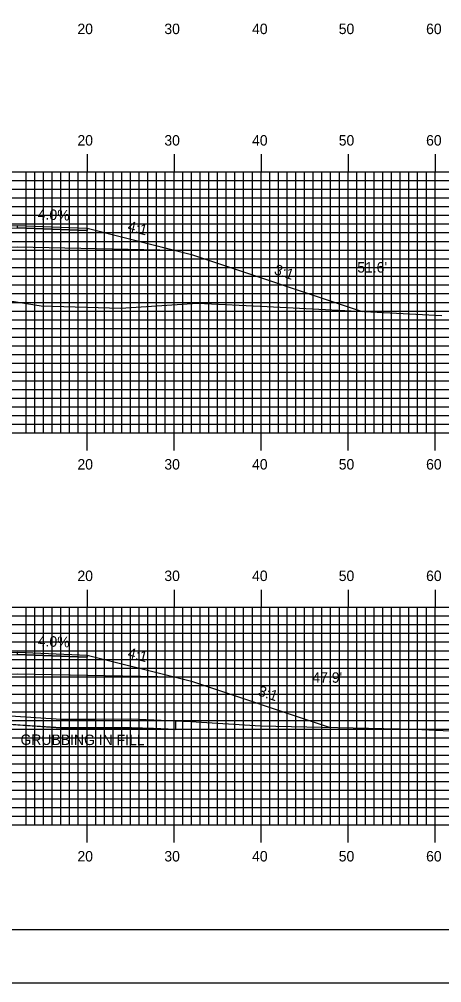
# Model space of a CAD drawing. Extents: x 1805471 to 1805814, y 442591 to 442811.
# Drawn here: x 1805648.9 to 1805697.5, y 442590.5 to 442701.2 of the extents above; entities that cross this region are included whole.
import ezdxf

# ---------------------------------------------------------------- set-up
doc = ezdxf.new("R2010")
doc.units = 0
for name, color, linetype in [('ANNOTATION', 7, 'Continuous'), ('BORDER', 7, 'Continuous'), ('D_Roadway_Centerline', 7, 'Continuous'), ('D_Roadway_Edge_Shoulder', 7, 'Continuous'), ('D_Roadway_SlopeLines', 7, 'Continuous'), ('D_Roadway_SubGrade', 7, 'Continuous'), ('D_Text_Standard', 7, 'Continuous'), ('GRUBBING IN FILL', 7, 'Continuous'), ('H_V ANNOTATION', 7, 'Continuous'), ('MAJOR', 7, 'Continuous'), ('MINOR', 7, 'Continuous'), ('PLOT BOUNDARY', 7, 'Continuous'), ('S_Roadway_Centerline', 7, 'Continuous')]:
    doc.layers.add(name, color=color, linetype=linetype)

msp = doc.modelspace()

# ---------------------------------------------------------------- linework, layer by layer
at = {"layer": 'BORDER'}
msp.add_lwpolyline([(1805487.11, 442596.67), (1805807.11, 442596.67), (1805807.11, 442806.67), (1805487.11, 442806.67)], close=True, dxfattribs=at)
at = {"layer": 'D_Roadway_Centerline'}
for points in [[(1805591.01, 442670.17), (1805604.71, 442673.6), (1805606.53, 442674.05), (1805616.71, 442676.6), (1805624.71, 442676.92), (1805636.71, 442677.21), (1805648.71, 442677.49), (1805656.71, 442677.17), (1805666.88, 442674.63), (1805668.71, 442674.17), (1805688.33, 442667.63)], [(1805599.16, 442623.21), (1805604.71, 442624.6), (1805606.53, 442625.05), (1805616.71, 442627.6), (1805624.71, 442627.92), (1805636.71, 442628.21), (1805648.71, 442628.49), (1805656.71, 442628.17), (1805666.88, 442625.63), (1805668.71, 442625.17), (1805684.65, 442619.86)]]:
    msp.add_lwpolyline(points, dxfattribs=at)
at = {"layer": 'D_Roadway_Edge_Shoulder'}
for points in [[(1805648.71, 442677.49), (1805656.71, 442677.17), (1805656.71, 442676.92), (1805648.71, 442677.24)], [(1805648.71, 442628.49), (1805656.71, 442628.17), (1805656.71, 442627.92), (1805648.71, 442628.24)]]:
    msp.add_lwpolyline(points, close=True, dxfattribs=at)
at = {"layer": 'D_Roadway_SlopeLines'}
for points in [[(1805656.71, 442677.17), (1805668.71, 442674.17), (1805688.33, 442667.63)], [(1805656.71, 442628.17), (1805668.71, 442625.17), (1805684.65, 442619.86)]]:
    msp.add_lwpolyline(points, dxfattribs=at)
at = {"layer": 'D_Roadway_SubGrade'}
for points in [[(1805624.71, 442674.42), (1805606.53, 442674.05), (1805616.71, 442676.6), (1805616.71, 442676.35), (1805624.71, 442676.67), (1805636.71, 442676.96), (1805648.71, 442677.24), (1805656.71, 442676.92), (1805656.71, 442677.17), (1805666.88, 442674.63), (1805648.71, 442674.99), (1805636.71, 442674.71)], [(1805624.71, 442625.42), (1805606.53, 442625.05), (1805616.71, 442627.6), (1805616.71, 442627.35), (1805624.71, 442627.67), (1805636.71, 442627.96), (1805648.71, 442628.24), (1805656.71, 442627.92), (1805656.71, 442628.17), (1805666.88, 442625.63), (1805648.71, 442625.99), (1805636.71, 442625.71)]]:
    msp.add_lwpolyline(points, close=True, dxfattribs=at)
at = {"layer": 'GRUBBING IN FILL'}
msp.add_line((1805666.88, 442620.62), (1805666.88, 442619.62), dxfattribs=at)
msp.add_line((1805666.88, 442620.62), (1805666.88, 442619.62), dxfattribs=at)
msp.add_lwpolyline([(1805606.53, 442621.76), (1805613.58, 442621.32), (1805617.1, 442621.11), (1805617.34, 442621.1), (1805617.7, 442621.08), (1805635.58, 442620.89), (1805644.34, 442620.45), (1805653.7, 442619.8), (1805661.81, 442619.83), (1805666.88, 442619.62)], dxfattribs=at)
msp.add_lwpolyline([(1805606.53, 442621.76), (1805613.58, 442621.32), (1805617.1, 442621.11), (1805617.34, 442621.1), (1805617.7, 442621.08), (1805635.58, 442620.89), (1805644.34, 442620.45), (1805653.7, 442619.8), (1805661.81, 442619.83), (1805666.88, 442619.62)], dxfattribs=at)
msp.add_lwpolyline([(1805636.71, 442621.83), (1805640.01, 442621.67), (1805644.4, 442621.44), (1805649.07, 442621.12), (1805653.73, 442620.8), (1805657.78, 442620.82), (1805661.83, 442620.83), (1805665.24, 442620.69), (1805666.88, 442620.62), (1805666.88, 442619.62), (1805664.35, 442619.73), (1805661.81, 442619.83), (1805657.76, 442619.82), (1805653.7, 442619.8), (1805649.02, 442620.12), (1805644.34, 442620.45), (1805639.96, 442620.67), (1805636.71, 442620.83)], close=True, dxfattribs=at)
msp.add_lwpolyline([(1805636.71, 442621.83), (1805640.01, 442621.67), (1805644.4, 442621.44), (1805649.07, 442621.12), (1805653.73, 442620.8), (1805657.78, 442620.82), (1805661.83, 442620.83), (1805665.24, 442620.69), (1805666.88, 442620.62), (1805666.88, 442619.62), (1805664.35, 442619.73), (1805661.81, 442619.83), (1805657.76, 442619.82), (1805653.7, 442619.8), (1805649.02, 442620.12), (1805644.34, 442620.45), (1805639.96, 442620.67), (1805636.71, 442620.83)], close=True, dxfattribs=at)
at = {"layer": 'MAJOR'}
for p, q in [((1805656.71, 442685.67), (1805656.71, 442683.67)), ((1805666.71, 442685.67), (1805666.71, 442683.67)), ((1805676.71, 442685.67), (1805676.71, 442683.67)), ((1805686.71, 442685.67), (1805686.71, 442683.67)), ((1805696.71, 442685.67), (1805696.71, 442683.67)), ((1805496.71, 442683.67), (1805776.71, 442683.67)), ((1805496.71, 442683.67), (1805776.71, 442683.67)), ((1805656.71, 442653.67), (1805656.71, 442683.67)), ((1805666.71, 442653.67), (1805666.71, 442683.67)), ((1805676.71, 442653.67), (1805676.71, 442683.67)), ((1805686.71, 442653.67), (1805686.71, 442683.67)), ((1805696.71, 442653.67), (1805696.71, 442683.67)), ((1805496.71, 442678.67), (1805776.71, 442678.67)), ((1805496.71, 442673.67), (1805776.71, 442673.67)), ((1805496.71, 442668.67), (1805776.71, 442668.67)), ((1805496.71, 442663.67), (1805776.71, 442663.67)), ((1805496.71, 442658.67), (1805776.71, 442658.67)), ((1805496.71, 442653.67), (1805776.71, 442653.67)), ((1805496.71, 442653.67), (1805776.71, 442653.67)), ((1805656.71, 442651.66), (1805656.71, 442653.67)), ((1805666.71, 442651.66), (1805666.71, 442653.67)), ((1805676.71, 442651.66), (1805676.71, 442653.67)), ((1805686.71, 442651.66), (1805686.71, 442653.67)), ((1805696.71, 442651.66), (1805696.71, 442653.67)), ((1805656.71, 442635.67), (1805656.71, 442633.67)), ((1805666.71, 442635.67), (1805666.71, 442633.67)), ((1805676.71, 442635.67), (1805676.71, 442633.67)), ((1805686.71, 442635.67), (1805686.71, 442633.67)), ((1805696.71, 442635.67), (1805696.71, 442633.67)), ((1805496.71, 442633.67), (1805776.71, 442633.67)), ((1805496.71, 442633.67), (1805776.71, 442633.67)), ((1805656.71, 442608.67), (1805656.71, 442633.67)), ((1805666.71, 442608.67), (1805666.71, 442633.67)), ((1805676.71, 442608.67), (1805676.71, 442633.67)), ((1805686.71, 442608.67), (1805686.71, 442633.67)), ((1805696.71, 442608.67), (1805696.71, 442633.67)), ((1805496.71, 442628.67), (1805776.71, 442628.67)), ((1805496.71, 442623.67), (1805776.71, 442623.67)), ((1805496.71, 442618.67), (1805776.71, 442618.67)), ((1805496.71, 442613.67), (1805776.71, 442613.67)), ((1805496.71, 442608.67), (1805776.71, 442608.67)), ((1805496.71, 442608.67), (1805776.71, 442608.67)), ((1805656.71, 442606.66), (1805656.71, 442608.67)), ((1805666.71, 442606.66), (1805666.71, 442608.67)), ((1805676.71, 442606.66), (1805676.71, 442608.67)), ((1805686.71, 442606.66), (1805686.71, 442608.67)), ((1805696.71, 442606.66), (1805696.71, 442608.67))]:
    msp.add_line(p, q, dxfattribs=at)
at = {"layer": 'MINOR'}
for p, q in [((1805649.71, 442653.67), (1805649.71, 442683.67)), ((1805650.71, 442653.67), (1805650.71, 442683.67)), ((1805651.71, 442653.67), (1805651.71, 442683.67)), ((1805652.71, 442653.67), (1805652.71, 442683.67)), ((1805653.71, 442653.67), (1805653.71, 442683.67)), ((1805654.71, 442653.67), (1805654.71, 442683.67)), ((1805655.71, 442653.67), (1805655.71, 442683.67)), ((1805657.71, 442653.67), (1805657.71, 442683.67)), ((1805658.71, 442653.67), (1805658.71, 442683.67)), ((1805659.71, 442653.67), (1805659.71, 442683.67)), ((1805660.71, 442653.67), (1805660.71, 442683.67)), ((1805661.71, 442653.67), (1805661.71, 442683.67)), ((1805662.71, 442653.67), (1805662.71, 442683.67)), ((1805663.71, 442653.67), (1805663.71, 442683.67)), ((1805664.71, 442653.67), (1805664.71, 442683.67)), ((1805665.71, 442653.67), (1805665.71, 442683.67)), ((1805667.71, 442653.67), (1805667.71, 442683.67)), ((1805668.71, 442653.67), (1805668.71, 442683.67)), ((1805669.71, 442653.67), (1805669.71, 442683.67)), ((1805670.71, 442653.67), (1805670.71, 442683.67)), ((1805671.71, 442653.67), (1805671.71, 442683.67)), ((1805672.71, 442653.67), (1805672.71, 442683.67)), ((1805673.71, 442653.67), (1805673.71, 442683.67)), ((1805674.71, 442653.67), (1805674.71, 442683.67)), ((1805675.71, 442653.67), (1805675.71, 442683.67)), ((1805677.71, 442653.67), (1805677.71, 442683.67)), ((1805678.71, 442653.67), (1805678.71, 442683.67)), ((1805679.71, 442653.67), (1805679.71, 442683.67)), ((1805680.71, 442653.67), (1805680.71, 442683.67)), ((1805681.71, 442653.67), (1805681.71, 442683.67)), ((1805682.71, 442653.67), (1805682.71, 442683.67)), ((1805683.71, 442653.67), (1805683.71, 442683.67)), ((1805684.71, 442653.67), (1805684.71, 442683.67)), ((1805685.71, 442653.67), (1805685.71, 442683.67)), ((1805687.71, 442653.67), (1805687.71, 442683.67)), ((1805688.71, 442653.67), (1805688.71, 442683.67)), ((1805689.71, 442653.67), (1805689.71, 442683.67)), ((1805690.71, 442653.67), (1805690.71, 442683.67)), ((1805691.71, 442653.67), (1805691.71, 442683.67)), ((1805692.71, 442653.67), (1805692.71, 442683.67)), ((1805693.71, 442653.67), (1805693.71, 442683.67)), ((1805694.71, 442653.67), (1805694.71, 442683.67)), ((1805695.71, 442653.67), (1805695.71, 442683.67)), ((1805496.71, 442682.67), (1805776.71, 442682.67)), ((1805496.71, 442681.67), (1805776.71, 442681.67)), ((1805496.71, 442680.67), (1805776.71, 442680.67)), ((1805496.71, 442679.67), (1805776.71, 442679.67)), ((1805496.71, 442677.67), (1805776.71, 442677.67)), ((1805496.71, 442676.67), (1805776.71, 442676.67)), ((1805496.71, 442675.67), (1805776.71, 442675.67)), ((1805496.71, 442674.67), (1805776.71, 442674.67)), ((1805496.71, 442672.67), (1805776.71, 442672.67)), ((1805496.71, 442671.67), (1805776.71, 442671.67)), ((1805496.71, 442670.67), (1805776.71, 442670.67)), ((1805496.71, 442669.67), (1805776.71, 442669.67)), ((1805496.71, 442667.67), (1805776.71, 442667.67)), ((1805496.71, 442666.67), (1805776.71, 442666.67)), ((1805496.71, 442665.67), (1805776.71, 442665.67)), ((1805496.71, 442664.67), (1805776.71, 442664.67)), ((1805496.71, 442662.67), (1805776.71, 442662.67)), ((1805496.71, 442661.67), (1805776.71, 442661.67)), ((1805496.71, 442660.67), (1805776.71, 442660.67)), ((1805496.71, 442659.67), (1805776.71, 442659.67)), ((1805496.71, 442657.67), (1805776.71, 442657.67)), ((1805496.71, 442656.67), (1805776.71, 442656.67)), ((1805496.71, 442655.67), (1805776.71, 442655.67)), ((1805496.71, 442654.67), (1805776.71, 442654.67)), ((1805649.71, 442608.67), (1805649.71, 442633.67)), ((1805650.71, 442608.67), (1805650.71, 442633.67)), ((1805651.71, 442608.67), (1805651.71, 442633.67)), ((1805652.71, 442608.67), (1805652.71, 442633.67)), ((1805653.71, 442608.67), (1805653.71, 442633.67)), ((1805654.71, 442608.67), (1805654.71, 442633.67)), ((1805655.71, 442608.67), (1805655.71, 442633.67)), ((1805657.71, 442608.67), (1805657.71, 442633.67)), ((1805658.71, 442608.67), (1805658.71, 442633.67)), ((1805659.71, 442608.67), (1805659.71, 442633.67)), ((1805660.71, 442608.67), (1805660.71, 442633.67)), ((1805661.71, 442608.67), (1805661.71, 442633.67)), ((1805662.71, 442608.67), (1805662.71, 442633.67)), ((1805663.71, 442608.67), (1805663.71, 442633.67)), ((1805664.71, 442608.67), (1805664.71, 442633.67)), ((1805665.71, 442608.67), (1805665.71, 442633.67)), ((1805667.71, 442608.67), (1805667.71, 442633.67)), ((1805668.71, 442608.67), (1805668.71, 442633.67)), ((1805669.71, 442608.67), (1805669.71, 442633.67)), ((1805670.71, 442608.67), (1805670.71, 442633.67)), ((1805671.71, 442608.67), (1805671.71, 442633.67)), ((1805672.71, 442608.67), (1805672.71, 442633.67)), ((1805673.71, 442608.67), (1805673.71, 442633.67)), ((1805674.71, 442608.67), (1805674.71, 442633.67)), ((1805675.71, 442608.67), (1805675.71, 442633.67)), ((1805677.71, 442608.67), (1805677.71, 442633.67)), ((1805678.71, 442608.67), (1805678.71, 442633.67)), ((1805679.71, 442608.67), (1805679.71, 442633.67)), ((1805680.71, 442608.67), (1805680.71, 442633.67)), ((1805681.71, 442608.67), (1805681.71, 442633.67)), ((1805682.71, 442608.67), (1805682.71, 442633.67)), ((1805683.71, 442608.67), (1805683.71, 442633.67)), ((1805684.71, 442608.67), (1805684.71, 442633.67)), ((1805685.71, 442608.67), (1805685.71, 442633.67)), ((1805687.71, 442608.67), (1805687.71, 442633.67)), ((1805688.71, 442608.67), (1805688.71, 442633.67)), ((1805689.71, 442608.67), (1805689.71, 442633.67)), ((1805690.71, 442608.67), (1805690.71, 442633.67)), ((1805691.71, 442608.67), (1805691.71, 442633.67)), ((1805692.71, 442608.67), (1805692.71, 442633.67)), ((1805693.71, 442608.67), (1805693.71, 442633.67)), ((1805694.71, 442608.67), (1805694.71, 442633.67)), ((1805695.71, 442608.67), (1805695.71, 442633.67)), ((1805496.71, 442632.67), (1805776.71, 442632.67)), ((1805496.71, 442631.67), (1805776.71, 442631.67)), ((1805496.71, 442630.67), (1805776.71, 442630.67)), ((1805496.71, 442629.67), (1805776.71, 442629.67)), ((1805496.71, 442627.67), (1805776.71, 442627.67)), ((1805496.71, 442626.67), (1805776.71, 442626.67)), ((1805496.71, 442625.67), (1805776.71, 442625.67)), ((1805496.71, 442624.67), (1805776.71, 442624.67)), ((1805496.71, 442622.67), (1805776.71, 442622.67)), ((1805496.71, 442621.67), (1805776.71, 442621.67)), ((1805496.71, 442620.67), (1805776.71, 442620.67)), ((1805496.71, 442619.67), (1805776.71, 442619.67)), ((1805496.71, 442617.67), (1805776.71, 442617.67)), ((1805496.71, 442616.67), (1805776.71, 442616.67)), ((1805496.71, 442615.67), (1805776.71, 442615.67)), ((1805496.71, 442614.67), (1805776.71, 442614.67)), ((1805496.71, 442612.67), (1805776.71, 442612.67)), ((1805496.71, 442611.67), (1805776.71, 442611.67)), ((1805496.71, 442610.67), (1805776.71, 442610.67)), ((1805496.71, 442609.67), (1805776.71, 442609.67))]:
    msp.add_line(p, q, dxfattribs=at)
at = {"layer": 'PLOT BOUNDARY'}
msp.add_lwpolyline([(1805470.92, 442590.55), (1805810.92, 442590.55), (1805810.92, 442810.55), (1805470.92, 442810.55)], close=True, dxfattribs=at)
at = {"layer": 'S_Roadway_Centerline'}
for points in [[(1805496.71, 442674.61), (1805505.87, 442674.02), (1805510.39, 442673.87), (1805525.71, 442673.8), (1805528.34, 442673.78), (1805550.84, 442672.02), (1805552.54, 442671.99), (1805554.11, 442671.93), (1805564.12, 442671.62), (1805575.81, 442670.91), (1805576.88, 442670.84), (1805596.88, 442669.9), (1805598.36, 442669.89), (1805600.11, 442669.9), (1805610.57, 442669.76), (1805632, 442669.48), (1805640.06, 442669.41), (1805645.87, 442669.15), (1805651.44, 442668.26), (1805660.58, 442667.99), (1805669.4, 442668.58), (1805677.43, 442668.19), (1805697.5, 442667.16)], [(1805583.63, 442624.03), (1805593.85, 442623.53), (1805596.58, 442623.37), (1805613.64, 442622.32), (1805617.16, 442622.11), (1805617.38, 442622.1), (1805617.72, 442622.08), (1805635.61, 442621.89), (1805644.4, 442621.44), (1805653.73, 442620.8), (1805661.83, 442620.83), (1805668.65, 442620.55), (1805676.66, 442620.03), (1805694.37, 442619.66), (1805700.06, 442619.38)]]:
    msp.add_lwpolyline(points, dxfattribs=at)

# ---------------------------------------------------------------- texts
at = {"layer": 'ANNOTATION'}
for s, rotation, p in [('-4.0%', 357.7094, (1805650.5, 442678.22)), ('4:1', 345.9638, (1805661.3, 442676.89)), ('3:1', 341.5652, (1805678.12, 442671.94)), ('-4.0%', 357.7094, (1805650.5, 442629.22)), ('4:1', 345.9638, (1805661.3, 442627.89)), ('3:1', 341.5652, (1805676.28, 442623.56))]:
    msp.add_text(s, height=1.2, rotation=rotation, dxfattribs=at).set_placement(p)
at = {"layer": 'D_Text_Standard'}
for s, p in [("51.6'", (1805687.77, 442672.09)), ("47.9'", (1805682.61, 442624.99))]:
    msp.add_text(s, height=1.2, dxfattribs=at).set_placement(p)
at = {"layer": 'GRUBBING IN FILL'}
msp.add_text('GRUBBING IN FILL', height=1.2, rotation=359.8053, dxfattribs=at).set_placement((1805649.06, 442617.86))
at = {"layer": 'H_V ANNOTATION'}
for s, p in [('20', (1805655.61, 442699.47)), ('30', (1805665.6, 442699.47)), ('40', (1805675.68, 442699.47)), ('50', (1805685.64, 442699.47)), ('60', (1805695.68, 442699.47)), ('20', (1805655.61, 442686.67)), ('30', (1805665.6, 442686.67)), ('40', (1805675.68, 442686.67)), ('50', (1805685.64, 442686.67)), ('60', (1805695.68, 442686.67)), ('20', (1805655.61, 442649.47)), ('30', (1805665.6, 442649.47)), ('40', (1805675.68, 442649.47)), ('50', (1805685.64, 442649.47)), ('60', (1805695.68, 442649.47)), ('20', (1805655.61, 442636.67)), ('30', (1805665.6, 442636.67)), ('40', (1805675.68, 442636.67)), ('50', (1805685.64, 442636.67)), ('60', (1805695.68, 442636.67)), ('20', (1805655.61, 442604.47)), ('30', (1805665.6, 442604.47)), ('40', (1805675.68, 442604.47)), ('50', (1805685.64, 442604.47)), ('60', (1805695.68, 442604.47))]:
    msp.add_text(s, height=1.2, dxfattribs=at).set_placement(p)

doc.saveas('drawing.dxf')
